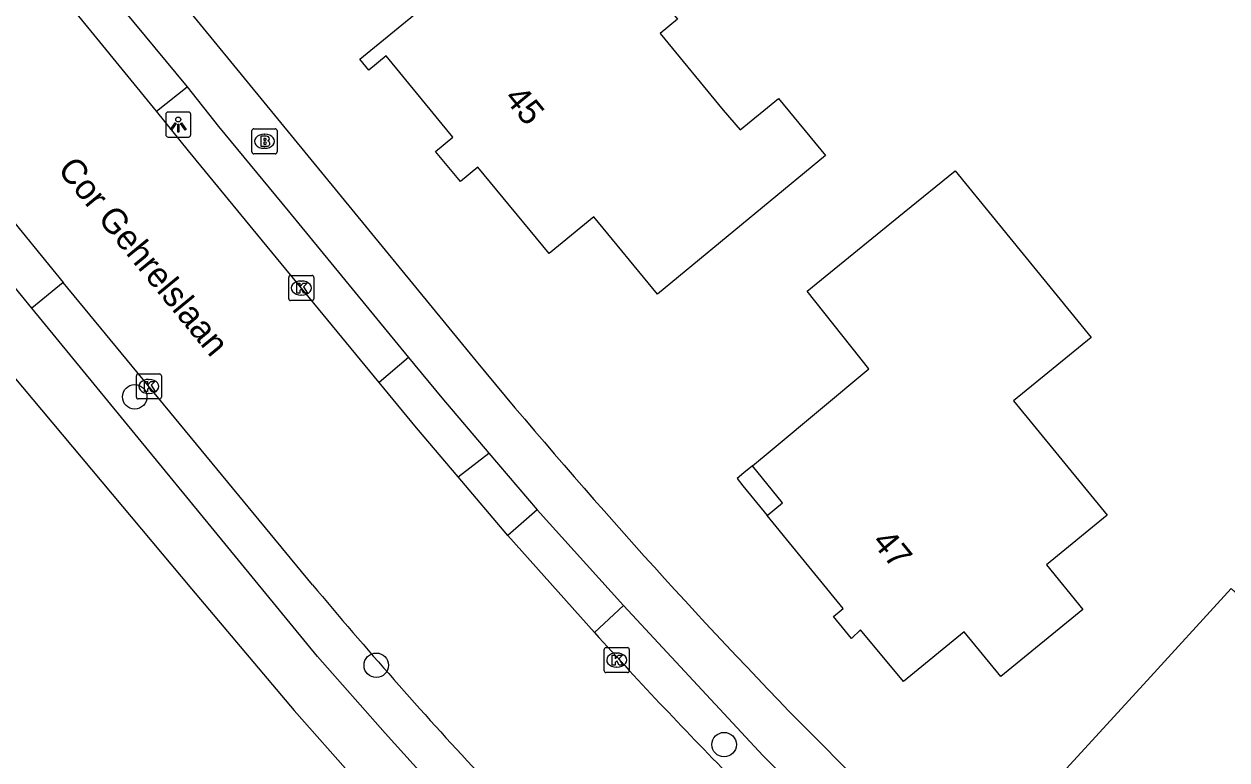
# Model space of a CAD drawing. Extents: x 157321 to 158827, y 386650 to 388532.
# Drawn here: x 158002.92 to 158050.96, y 387250.99 to 387280.38 of the extents above; entities that cross this region are included whole.
import ezdxf

# ---------------------------------------------------------------- set-up
doc = ezdxf.new("R2010")
doc.units = 0
for name, color, linetype in [('IMGEO_Boom', 7, 'Continuous'), ('IMGEO_Brandkraan', 7, 'Continuous'), ('IMGEO_Kolk', 7, 'Continuous'), ('IMGEO_Lichtpunt', 7, 'Continuous'), ('IMGEO_Openbare_ruimte_label', 7, 'Continuous'), ('IMGEO_Pand', 7, 'Continuous'), ('IMGEO_Pand_nummerreeks', 7, 'Continuous'), ('IMGEO_Pand_overbouw', 7, 'Continuous'), ('IMGEO_Rijbaan_lokaal_gesloten', 7, 'Continuous'), ('IMGEO_Voetpad_open', 7, 'Continuous')]:
    doc.layers.add(name, color=color, linetype=linetype)

msp = doc.modelspace()

# ---------------------------------------------------------------- linework, layer by layer
at = {"layer": 'IMGEO_Boom'}
for centre in [(158007.337, 387265.491), (158016.984, 387254.77), (158030.877, 387251.601)]:
    msp.add_circle(centre, 0.489, dxfattribs=at)
at = {"layer": 'IMGEO_Brandkraan'}
for p, q in [((158012.02, 387275.27), (158012.02, 387276.122)), ((158012.095, 387276.196), (158012.947, 387276.196)), ((158013.021, 387276.122), (158013.021, 387275.27)), ((158012.508, 387275.976), (158012.533, 387275.976)), ((158012.947, 387275.196), (158012.095, 387275.196)), ((158012.531, 387275.416), (158012.506, 387275.416))]:
    msp.add_line(p, q, dxfattribs=at)
for points in [[(158012.02, 387275.27), (158012.02, 387276.122)], [(158012.095, 387276.196), (158012.947, 387276.196)], [(158013.021, 387276.122), (158013.021, 387275.27)], [(158012.368, 387275.896), (158012.368, 387275.496), (158012.581, 387275.496)], [(158012.599, 387275.896), (158012.368, 387275.896)], [(158012.547, 387275.815), (158012.493, 387275.815), (158012.493, 387275.739)], [(158012.493, 387275.739), (158012.546, 387275.739)], [(158012.555, 387275.663), (158012.493, 387275.663), (158012.493, 387275.582)], [(158012.493, 387275.582), (158012.555, 387275.582)], [(158012.947, 387275.196), (158012.095, 387275.196)]]:
    msp.add_lwpolyline(points, dxfattribs=at)
for centre, radius, start, end in [((158012.097, 387276.12), 0.0765, 91.552, 178.448), ((158012.097, 387276.12), 0.0765, 91.552, 178.448), ((158012.945, 387276.12), 0.0765, 1.552, 88.448), ((158012.945, 387276.12), 0.0765, 1.552, 88.448), ((158012.548, 387275.777), 0.0379, 267.8285, 90.9355), ((158012.556, 387275.622), 0.0404, 269.8759, 90.5077), ((158012.587, 387275.747), 0.251, 268.6676, 293.5347), ((158012.603, 387275.751), 0.145, 59.4692, 91.5367), ((158012.628, 387275.798), 0.0922, 285.5137, 58.1501), ((158012.633, 387275.606), 0.105, 301.3115, 78.989), ((158012.097, 387275.272), 0.0765, 181.552, 268.448), ((158012.097, 387275.272), 0.0765, 181.552, 268.448), ((158012.945, 387275.272), 0.0765, 271.552, 358.448), ((158012.945, 387275.272), 0.0765, 271.552, 358.448)]:
    msp.add_arc(centre, radius, start, end, dxfattribs=at)
for centre, major_axis, ratio, start_param, end_param in [((158012.507, 387275.696), (-0.387, 0.002), 0.722429, 4.712389, 7.853982), ((158012.532, 387275.696), (-0.39, 0.002), 0.717154, 1.570796, 4.712389)]:
    msp.add_ellipse(centre, major_axis=major_axis, ratio=ratio, start_param=start_param, end_param=end_param, dxfattribs=at)
at = {"layer": 'IMGEO_Kolk'}
for p, q in [((158013.489, 387269.411), (158013.489, 387270.263)), ((158013.564, 387270.337), (158014.416, 387270.337)), ((158014.49, 387270.263), (158014.49, 387269.411)), ((158013.977, 387270.117), (158014.002, 387270.117)), ((158014.416, 387269.337), (158013.564, 387269.337)), ((158014, 387269.557), (158013.975, 387269.557)), ((158007.477, 387266.407), (158008.329, 387266.407)), ((158007.402, 387265.481), (158007.402, 387266.333)), ((158007.89, 387266.187), (158007.915, 387266.187)), ((158008.403, 387266.333), (158008.403, 387265.481)), ((158007.913, 387265.627), (158007.888, 387265.627)), ((158008.329, 387265.407), (158007.477, 387265.407)), ((158026.086, 387254.553), (158026.086, 387255.405)), ((158026.161, 387255.479), (158027.013, 387255.479)), ((158027.087, 387255.405), (158027.087, 387254.553)), ((158026.574, 387255.259), (158026.599, 387255.259)), ((158027.013, 387254.479), (158026.161, 387254.479)), ((158026.597, 387254.699), (158026.572, 387254.699))]:
    msp.add_line(p, q, dxfattribs=at)
for points in [[(158013.489, 387269.411), (158013.489, 387270.263)], [(158013.564, 387270.337), (158014.416, 387270.337)], [(158014.49, 387270.263), (158014.49, 387269.411)], [(158013.81, 387270.037), (158013.933, 387270.037), (158013.933, 387269.886), (158014.063, 387270.037), (158014.227, 387270.037), (158014.081, 387269.886), (158014.234, 387269.637), (158014.082, 387269.637), (158013.997, 387269.801), (158013.933, 387269.734), (158013.933, 387269.637), (158013.81, 387269.637), (158013.81, 387270.037)], [(158014.416, 387269.337), (158013.564, 387269.337)], [(158007.477, 387266.407), (158008.329, 387266.407)], [(158007.402, 387265.481), (158007.402, 387266.333)], [(158007.723, 387266.107), (158007.846, 387266.107), (158007.846, 387265.956), (158007.976, 387266.107), (158008.14, 387266.107), (158007.994, 387265.956), (158008.147, 387265.707), (158007.995, 387265.707), (158007.91, 387265.871), (158007.846, 387265.804), (158007.846, 387265.707), (158007.723, 387265.707), (158007.723, 387266.107)], [(158008.403, 387266.333), (158008.403, 387265.481)], [(158008.329, 387265.407), (158007.477, 387265.407)], [(158026.086, 387254.553), (158026.086, 387255.405)], [(158026.161, 387255.479), (158027.013, 387255.479)], [(158027.087, 387255.405), (158027.087, 387254.553)], [(158026.407, 387255.179), (158026.53, 387255.179), (158026.53, 387255.028), (158026.66, 387255.179), (158026.824, 387255.179), (158026.678, 387255.028), (158026.831, 387254.779), (158026.679, 387254.779), (158026.594, 387254.943), (158026.53, 387254.876), (158026.53, 387254.779), (158026.407, 387254.779), (158026.407, 387255.179)], [(158027.013, 387254.479), (158026.161, 387254.479)]]:
    msp.add_lwpolyline(points, dxfattribs=at)
for centre, start, end in [((158013.566, 387270.261), 91.552, 178.448), ((158013.566, 387270.261), 91.552, 178.448), ((158014.414, 387270.261), 1.552, 88.448), ((158014.414, 387270.261), 1.552, 88.448), ((158013.566, 387269.413), 181.552, 268.448), ((158013.566, 387269.413), 181.552, 268.448), ((158014.414, 387269.413), 271.552, 358.448), ((158014.414, 387269.413), 271.552, 358.448), ((158007.479, 387266.331), 91.552, 178.448), ((158007.479, 387266.331), 91.552, 178.448), ((158008.327, 387266.331), 1.552, 88.448), ((158008.327, 387266.331), 1.552, 88.448), ((158007.479, 387265.483), 181.552, 268.448), ((158007.479, 387265.483), 181.552, 268.448), ((158008.327, 387265.483), 271.552, 358.448), ((158008.327, 387265.483), 271.552, 358.448), ((158026.163, 387255.403), 91.552, 178.448), ((158026.163, 387255.403), 91.552, 178.448), ((158027.011, 387255.403), 1.552, 88.448), ((158027.011, 387255.403), 1.552, 88.448), ((158026.163, 387254.555), 181.552, 268.448), ((158026.163, 387254.555), 181.552, 268.448), ((158027.011, 387254.555), 271.552, 358.448), ((158027.011, 387254.555), 271.552, 358.448)]:
    msp.add_arc(centre, 0.0765, start, end, dxfattribs=at)
for centre, major_axis, ratio, start_param, end_param in [((158013.976, 387269.837), (-0.387, 0.002), 0.722429, 4.712389, 7.853982), ((158014.001, 387269.837), (-0.39, 0.002), 0.717154, 1.570796, 4.712389), ((158007.889, 387265.907), (-0.387, 0.002), 0.722429, 4.712389, 7.853982), ((158007.914, 387265.907), (-0.39, 0.002), 0.717154, 1.570796, 4.712389), ((158026.573, 387254.979), (-0.387, 0.002), 0.722429, 4.712389, 7.853982), ((158026.598, 387254.979), (-0.39, 0.002), 0.717154, 1.570796, 4.712389)]:
    msp.add_ellipse(centre, major_axis=major_axis, ratio=ratio, start_param=start_param, end_param=end_param, dxfattribs=at)
at = {"layer": 'IMGEO_Lichtpunt'}
for p, q in [((158008.577, 387276.769), (158008.577, 387275.962)), ((158008.577, 387276.769), (158008.577, 387275.962)), ((158009.479, 387276.864), (158008.671, 387276.864)), ((158009.479, 387276.864), (158008.671, 387276.864)), ((158009.573, 387275.962), (158009.573, 387276.769)), ((158009.573, 387275.962), (158009.573, 387276.769)), ((158008.671, 387275.868), (158009.479, 387275.868)), ((158008.671, 387275.868), (158009.479, 387275.868))]:
    msp.add_line(p, q, dxfattribs=at)
for points in [[(158008.951, 387276.433), (158008.99, 387276.405), (158008.802, 387276.143), (158008.764, 387276.17), (158008.951, 387276.433)], [(158009.053, 387276.385), (158009.1, 387276.385), (158009.1, 387276.063), (158009.053, 387276.063), (158009.053, 387276.385)], [(158009.163, 387276.405), (158009.201, 387276.432), (158009.388, 387276.17), (158009.349, 387276.142), (158009.163, 387276.405)]]:
    msp.add_lwpolyline(points, dxfattribs=at)
msp.add_circle((158009.076, 387276.567), 0.0994, dxfattribs=at)
for centre, start, end in [((158008.671, 387276.769), 90, 180), ((158008.671, 387276.769), 90, 180), ((158009.479, 387276.769), 0, 90), ((158009.479, 387276.769), 0, 90), ((158008.671, 387275.962), 180, 270), ((158008.671, 387275.962), 180, 270), ((158009.479, 387275.962), 270, 0), ((158009.479, 387275.962), 270, 360)]:
    msp.add_arc(centre, 0.0946, start, end, dxfattribs=at)
at = {"layer": 'IMGEO_Pand'}
for points in [[(158028.216, 387269.592), (158025.669, 387272.677), (158023.895, 387271.214), (158021.044, 387274.668), (158020.35, 387274.095), (158019.349, 387275.291), (158020.037, 387275.862), (158017.382, 387279.115), (158016.685, 387278.541), (158016.331, 387278.976), (158020.194, 387282.151), (158024.676, 387285.834), (158029.015, 387280.57), (158028.32, 387279.997), (158030.84, 387276.941), (158031.512, 387276.15), (158033.043, 387277.412), (158034.928, 387275.127), (158028.216, 387269.592)], [(158045.536, 387267.864), (158042.435, 387265.326), (158046.172, 387260.759), (158043.755, 387258.784), (158045.209, 387257.004), (158041.925, 387254.321), (158040.47, 387256.101), (158038.045, 387254.121), (158036.328, 387256.186), (158035.96, 387255.846), (158035.247, 387256.719), (158035.633, 387257.035), (158032.594, 387260.758), (158033.211, 387261.262), (158032.006, 387262.738), (158032.794, 387263.394), (158036.658, 387266.612), (158034.188, 387269.705), (158038.068, 387272.86), (158040.106, 387274.518), (158045.536, 387267.864)], [(158061.754, 387245.899), (158062.835, 387247.078), (158063.056, 387246.875), (158059.33, 387242.81), (158055.951, 387239.123), (158055.746, 387239.318), (158055.971, 387239.557), (158052.433, 387242.815), (158050.229, 387244.844), (158049.216, 387243.74), (158045.89, 387246.777), (158046.898, 387247.888), (158044.591, 387250), (158044.243, 387250.319), (158047.62, 387254.007), (158051.13, 387257.841), (158056.652, 387252.764), (158055.57, 387251.584), (158061.754, 387245.899)]]:
    msp.add_lwpolyline(points, dxfattribs=at)
at = {"layer": 'IMGEO_Pand_overbouw'}
msp.add_lwpolyline([(158032.594, 387260.758), (158033.211, 387261.262), (158032.006, 387262.738), (158031.668, 387262.457), (158031.392, 387262.235), (158031.63, 387261.939)], close=True, dxfattribs=at)
at = {"layer": 'IMGEO_Rijbaan_lokaal_gesloten'}
for points in [[(158008.212, 387276.901), (158004.449, 387281.5)], [(158017.101, 387266.07), (158012.256, 387271.943), (158009.486, 387275.32), (158008.212, 387276.901)], [(158001.953, 387273.145), (158004.474, 387270.061)], [(158014.434, 387257.989), (158004.474, 387270.061)], [(158020.261, 387262.291), (158018.597, 387264.257), (158017.101, 387266.07)], [(158022.244, 387259.949), (158020.261, 387262.291)], [(158022.244, 387259.949), (158025.703, 387256.074)]]:
    msp.add_lwpolyline(points, dxfattribs=at)
for centre, radius, start, end in [((158161.801, 387381.247), 192.119, 219.90923, 222.88697), ((158166.946, 387383.963), 190.539, 222.15946, 224.615)]:
    msp.add_arc(centre, radius, start, end, dxfattribs=at)
at = {"layer": 'IMGEO_Voetpad_open'}
for points in [[(157999.612, 387292.962), (158000.785, 387291.532), (158020.97, 387266.911)], [(158005.629, 387282.478), (158009.429, 387277.867)], [(158008.212, 387276.901), (158009.429, 387277.867)], [(158009.429, 387277.867), (158010.687, 387276.293), (158013.471, 387272.92), (158018.276, 387267.066)], [(158003.224, 387269.036), (158000.735, 387272.069)], [(158004.474, 387270.061), (158003.224, 387269.036)], [(158024.7, 387244.176), (158019.965, 387249.158), (158019.205, 387250), (158017.345, 387252.062), (158014.64, 387255.124), (158003.224, 387269.036)], [(158018.276, 387267.066), (158017.101, 387266.07)], [(158018.276, 387267.066), (158019.602, 387265.45), (158021.481, 387263.247)], [(158002.445, 387266.373), (158009.6, 387257.817), (158013.703, 387252.963), (158016.061, 387250.304), (158016.341, 387250), (158020.077, 387245.943)], [(158020.261, 387262.291), (158021.481, 387263.247)], [(158021.481, 387263.247), (158023.416, 387260.98)], [(158023.416, 387260.98), (158022.244, 387259.949)], [(158023.416, 387260.98), (158026.857, 387257.158)], [(158025.703, 387256.074), (158026.857, 387257.158)], [(158026.857, 387257.158), (158032.44, 387251.155), (158033.601, 387250), (158039.142, 387244.637)], [(158033.883, 387252.507), (158036.396, 387250)]]:
    msp.add_lwpolyline(points, dxfattribs=at)
msp.add_arc((158210.543, 387423.871), 246.118, 219.62353, 224.12811, dxfattribs=at)

# ---------------------------------------------------------------- texts
at = {"layer": 'IMGEO_Openbare_ruimte_label'}
msp.add_text('Cor Gehrelslaan', height=1, rotation=309.358, dxfattribs=at).set_placement((158004.224, 387274.554))
at = {"layer": 'IMGEO_Pand_nummerreeks'}
for s, rotation, p in [('45', 309.4995, (158022.057, 387277.405)), ('47', 309.3964, (158036.743, 387259.678))]:
    msp.add_text(s, height=1, rotation=rotation, dxfattribs=at).set_placement(p)

doc.saveas('drawing.dxf')
